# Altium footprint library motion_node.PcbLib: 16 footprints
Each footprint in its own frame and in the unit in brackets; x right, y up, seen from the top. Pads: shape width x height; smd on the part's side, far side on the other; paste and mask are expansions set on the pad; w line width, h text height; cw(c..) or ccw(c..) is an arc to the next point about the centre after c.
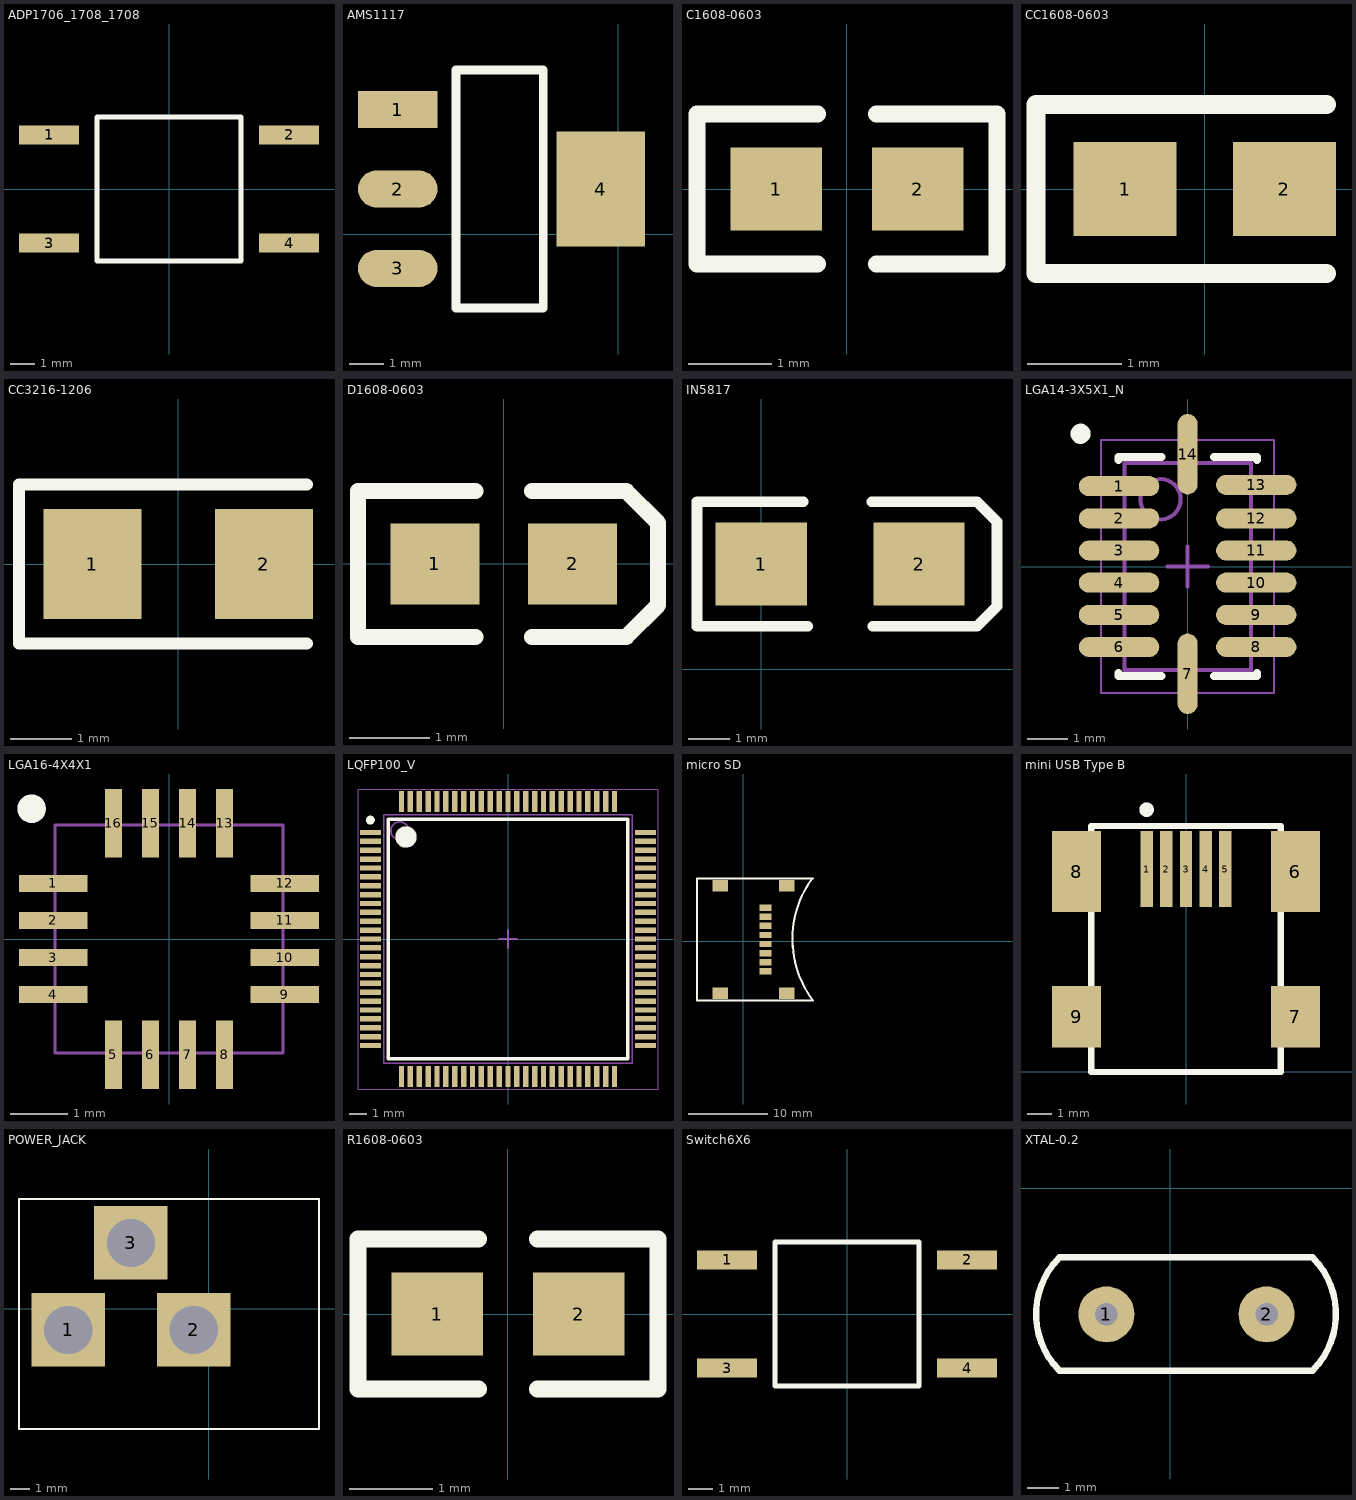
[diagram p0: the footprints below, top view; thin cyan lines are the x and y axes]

## ADP1706_1708_1708 [mm] "Linear Regulator"
pads (4):
  rect 2.5x0.8 smd: 1(-5,2.25) 2(5,2.25) 3(-5,-2.25) 4(5,-2.25)
Top Overlay:
  lines w0.2: -3,-3 -3,3 3,3 3,-3 -3,-3

## AMS1117 [mil]
pads (4):
  rect 90x42 smd: 1(-250,141)
  oval 90x42 smd: 2(-250,51) 3(-250,-39)
  rect 100x130 smd: 4(-20,51)
Top Overlay:
  lines w10: -99,186 -184,186 -184,-84 -85,-84 -85,186 -97.5,186

## C1608-0603 [mm]
pads (2):
  rect 1.1x1 smd: 1(-0.85,0) 2(0.85,0)
Top Overlay:
  lines w0.2: -0.35,-0.9 -1.8,-0.9 -1.8,0.9 -0.35,0.9 ; 0.35,-0.9 1.8,-0.9 1.8,0.9 0.35,0.9

## CC1608-0603 [mm]
pads (2):
  rect 1.1x1 smd: 1(-0.85,0) 2(0.85,0)
Top Overlay:
  lines w0.2: 1.3,-0.9 -1.8,-0.9 -1.8,0.9 1.3,0.9

## CC3216-1206 [mm]
pads (2):
  rect 1.6x1.8 smd: 1(-1.4,0) 2(1.4,0)
Top Overlay:
  lines w0.2: 2.1,-1.3 -2.6,-1.3 -2.6,1.3 2.1,1.3

## D1608-0603 [mm]
pads (2):
  rect 1.1x1 smd: 1(-0.85,0) 2(0.85,0)
Top Overlay:
  lines w0.2: -0.35,-0.9 -1.8,-0.9 -1.8,0.9 -0.35,0.9 ; 0.35,-0.9 1.513,-0.9 1.905,-0.508 1.905,0.508 1.513,0.9 0.35,0.9

## IN5817 [mm]
pads (2):
  rect 2.2x2 smd: 1(0,2.54) 2(3.81,2.54)
Top Overlay:
  lines w0.254: 1.016,4.039 -1.549,4.039 -1.549,1.041 1.118,1.041 ; 2.667,4.039 5.207,4.039 5.69,3.556 5.69,1.524 5.207,1.041 2.692,1.041

## LGA14-3X5X1_N [mm] "PQFN, 14-Leads, Body 3x5mm, Pitch 0.8mm, IPC Medium Density"
height 1
pads (14):
  oval 2x0.5 smd: 1(-1.706,2) 2(-1.706,1.2) 3(-1.706,0.4) 4(-1.706,-0.4) 5(-1.706,-1.2) 6(-1.706,-2) 8(1.706,-2) 9(1.706,-1.2) 10(1.706,-0.4) 11(1.706,0.4) 12(1.706,1.2) 13(1.706,2.032)
  oval 0.5x2 smd: 7(0,-2.667) 14(0,2.794)
Top Overlay:
  circle w0.25: c-2.665,3.302 r0.125
  lines w0.2: -1.725,-2.65 -1.725,-2.725 -0.65,-2.725 ; -1.725,2.65 -1.725,2.725 -0.65,2.725 ; 0.65,-2.725 1.725,-2.725 1.725,-2.65 ; 0.65,2.725 1.725,2.725 1.725,2.65
Mechanical 13:
  circle w0.1: c-0.675,1.675 r0.5
  lines w0.1: -1.575,-2.575 1.575,-2.575 1.575,2.575 -1.575,2.575 -1.575,-2.575
Mechanical 15:
  lines w0.05: -2.15,-3.15 2.15,-3.15 2.15,3.15 -2.15,3.15 -2.15,-3.15
  lines w0.1: -0.5,0 0.5,0 ; 0,-0.5 0,0.5
3D body: height 1, standoff 0, extent -1.575,-2.575 1.575,2.575

## LGA16-4X4X1 [mm]
height 1
pads (16):
  rect 1.2x0.3 smd: 1(-2.032,0.975) 2(-2.032,0.325) 3(-2.032,-0.325) 4(-2.032,-0.975) 9(2.032,-0.975) 10(2.032,-0.325) 11(2.032,0.325) 12(2.032,0.975)
  rect 0.3x1.2 smd: 5(-0.975,-2.032) 6(-0.325,-2.032) 7(0.325,-2.032) 8(0.975,-2.032) 13(0.975,2.032) 14(0.325,2.032) 15(-0.325,2.032) 16(-0.975,2.032)
Top Overlay:
  circle w0.25: c-2.411,2.286 r0.125
Mechanical 15:
  lines w0.05: -2,-2 -2,2 2,2 2,-2 -2,-2

## LQFP100_V [mm] "Thin QFP, 100-Leads, Body 14x14mm, Pitch 0.5mm, ST Recommended"
height 1.6
pads (100):
  rect 1.2x0.3 smd: 1(-7.75,6) 2(-7.75,5.5) 3(-7.75,5) 4(-7.75,4.5) 5(-7.75,4) 6(-7.75,3.5) 7(-7.75,3) 8(-7.75,2.5) 9(-7.75,2) 10(-7.75,1.5) 11(-7.75,1) 12(-7.75,0.5) 13(-7.75,0) 14(-7.75,-0.5) 15(-7.75,-1) 16(-7.75,-1.5) 17(-7.75,-2) 18(-7.75,-2.5) 19(-7.75,-3) 20(-7.75,-3.5) 21(-7.75,-4) 22(-7.75,-4.5) 23(-7.75,-5) 24(-7.75,-5.5) 25(-7.75,-6) 51(7.75,-6) 52(7.75,-5.5) 53(7.75,-5) 54(7.75,-4.5) 55(7.75,-4) 56(7.75,-3.5) 57(7.75,-3) 58(7.75,-2.5) 59(7.75,-2) 60(7.75,-1.5) 61(7.75,-1) 62(7.75,-0.5) 63(7.75,0) 64(7.75,0.5) 65(7.75,1) 66(7.75,1.5) 67(7.75,2) 68(7.75,2.5) 69(7.75,3) 70(7.75,3.5) 71(7.75,4) 72(7.75,4.5) 73(7.75,5) 74(7.75,5.5) 75(7.75,6)
  rect 0.3x1.2 smd: 26(-6,-7.75) 27(-5.5,-7.75) 28(-5,-7.75) 29(-4.5,-7.75) 30(-4,-7.75) 31(-3.5,-7.75) 32(-3,-7.75) 33(-2.5,-7.75) 34(-2,-7.75) 35(-1.5,-7.75) 36(-1,-7.75) 37(-0.5,-7.75) 38(0,-7.75) 39(0.5,-7.75) 40(1,-7.75) 41(1.5,-7.75) 42(2,-7.75) 43(2.5,-7.75) 44(3,-7.75) 45(3.5,-7.75) 46(4,-7.75) 47(4.5,-7.75) 48(5,-7.75) 49(5.5,-7.75) 50(6,-7.75) 76(6,7.75) 77(5.5,7.75) 78(5,7.75) 79(4.5,7.75) 80(4,7.75) 81(3.5,7.75) 82(3,7.75) 83(2.5,7.75) 84(2,7.75) 85(1.5,7.75) 86(1,7.75) 87(0.5,7.75) 88(0,7.75) 89(-0.5,7.75) 90(-1,7.75) 91(-1.5,7.75) 92(-2,7.75) 93(-2.5,7.75) 94(-3,7.75) 95(-3.5,7.75) 96(-4,7.75) 97(-4.5,7.75) 98(-5,7.75) 99(-5.5,7.75) 100(-6,7.75)
Top Overlay:
  circle w0.6: c-5.75,5.75 r0.3
  circle w0.25: c-7.75,6.7 r0.125
  lines w0.2: -6.75,-6.75 6.75,-6.75 6.75,6.75 -6.75,6.75 -6.75,-6.75
Mechanical 13:
  circle w0.1: c-6.1,6.1 r0.5
  lines w0.1: -7,-7 7,-7 7,7 -7,7 -7,-7
Mechanical 15:
  lines w0.05: -8.45,-8.45 8.45,-8.45 8.45,8.45 -8.45,8.45 -8.45,-8.45
  lines w0.1: -0.5,0 0.5,0 ; 0,-0.5 0,0.5
3D body: height 1.6, standoff 0.05, extent -7,-7 7,7

## micro SD [mm]
pads (12):
  rect 1.5x0.8 smd: 1(2.794,4.191) 2(2.794,3.048) 3(2.794,1.905) 4(2.794,0.762) 5(2.794,-0.381) 6(2.794,-1.524) 7(2.794,-2.667) 8(2.794,-3.81)
  rect 2x1.45 smd: ""(-2.921,-6.604) ""(-2.921,6.985) ""(5.461,-6.604) ""(5.461,6.985)
Top Overlay:
  lines w0.254: 8.614,7.798 ccw(c19.05,0.254) 8.763,-7.493 -5.842,-7.493 -5.842,7.874 8.763,7.874

## mini USB Type B [mm]
pads (9):
  rect 0.5x3.1 smd: 1(-1.6,8.25) 2(-0.8,8.25) 3(0,8.25) 4(0.8,8.25) 5(1.6,8.25)
  rect 2x3.3 smd: 6(4.45,8.15) 8(-4.45,8.15)
  rect 2x2.5 smd: 7(4.45,2.25) 9(-4.45,2.25)
Top Overlay:
  circle w0.3: c-1.6,10.668 r0.146
  lines w0.254: -3.85,0 3.85,0 3.85,10 -3.85,10 -3.85,0

## POWER_JACK [mm]
pads (3):
  rect 3.8x3.8 hole 2.5: 1(-7.264,-1.092) 2(-0.764,-1.092) 3(-4.014,3.408)
Top Overlay:
  lines w0.102: -9.804,-6.223 5.715,-6.223 5.715,5.69 -9.804,5.69 -9.804,-6.223

## R1608-0603 [mm]
pads (2):
  rect 1.1x1 smd: 1(-0.85,0) 2(0.85,0)
Top Overlay:
  lines w0.2: -0.35,-0.9 -1.8,-0.9 -1.8,0.9 -0.35,0.9 ; 0.35,-0.9 1.8,-0.9 1.8,0.9 0.35,0.9

## Switch6X6 [mm]
pads (4):
  rect 2.5x0.8 smd: 1(-5,2.25) 2(5,2.25) 3(-5,-2.25) 4(5,-2.25)
Top Overlay:
  lines w0.2: -3,-3 3,-3 3,3 -3,3 -3,-3

## XTAL-0.2 [mil]
height 149.61
pads (2):
  round 70 hole 28: 1(-79.92,-157.48) 2(120.08,-157.48)
Top Overlay:
  lines w8: 177.41,-227.79 -138.63,-227.79 cw(c-67.92,-157.08) -138.63,-86.37 177.41,-86.37 ; 177.48,-227.72 ccw(c106.77,-157.01) 177.48,-86.3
